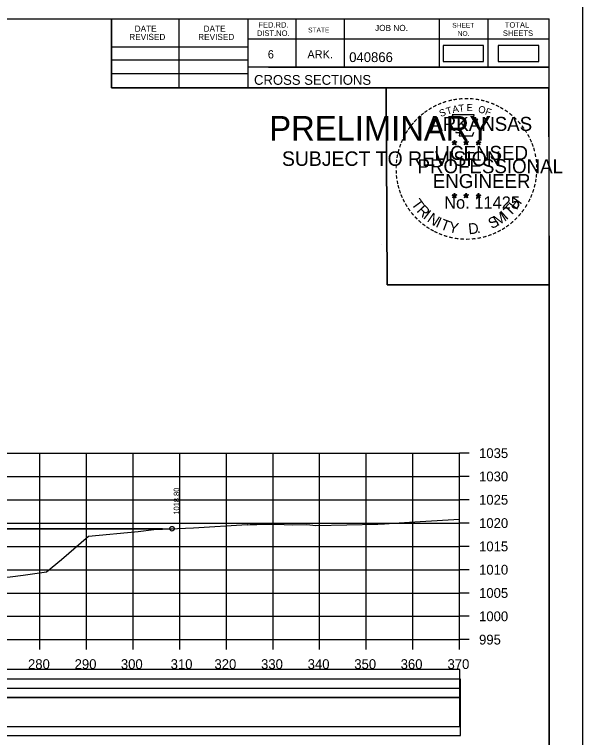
# Model space of a CAD drawing. Extents: x 1370565 to 1374448, y 301010 to 304637.
# Drawn here: x 1374326 to 1374447.9, y 301573 to 301728.1 of the extents above; entities that cross this region are included whole.
import ezdxf

# ---------------------------------------------------------------- set-up
doc = ezdxf.new("R2010")
doc.units = 0
for name, color, linetype in [('Default', 7, 'Continuous'), ('R_Axis', 7, 'Continuous'), ('R_Axis Annot', 7, 'Continuous'), ('R_Border', 7, 'Continuous'), ('R_Border PE', 7, 'Continuous'), ('R_Border Prem', 7, 'Continuous'), ('R_Contours', 7, 'Continuous'), ('R_Drive', 7, 'Continuous'), ('R_Exist Surface', 7, 'Continuous'), ('R_Fin Surface', 7, 'Continuous'), ('R_Grid', 7, 'Continuous'), ('R_No Plot', 7, 'Continuous'), ('R_Xsect Elev', 7, 'Continuous')]:
    doc.layers.add(name, color=color, linetype=linetype)

msp = doc.modelspace()

# ---------------------------------------------------------------- linework, layer by layer
at = {"layer": 'Default'}
for points in [[(1374418.01, 301717.94), (1374426.7, 301717.94), (1374426.7, 301721.38), (1374418.01, 301721.38)], [(1373981.44, 301583.58), (1374421.61, 301583.58), (1374421.61, 301587.57), (1373981.44, 301587.57)], [(1373981.44, 301575.36), (1374421.61, 301575.36), (1374421.61, 301583.5), (1373981.44, 301583.5)]]:
    msp.add_lwpolyline(points, close=True, dxfattribs=at)
at = {"layer": 'R_Axis'}
for p, q in [((1374421.52, 301593.96), (1374421.52, 301633.96)), ((1374423.62, 301633.96), (1374421.52, 301633.96)), ((1374423.62, 301628.96), (1374421.52, 301628.96)), ((1374423.62, 301623.96), (1374421.52, 301623.96)), ((1374423.62, 301618.96), (1374421.52, 301618.96)), ((1374423.62, 301613.96), (1374421.52, 301613.96)), ((1374423.62, 301608.96), (1374421.52, 301608.96)), ((1374423.62, 301603.96), (1374421.52, 301603.96)), ((1374423.62, 301598.96), (1374421.52, 301598.96)), ((1373981.52, 301593.96), (1374421.52, 301593.96)), ((1374331.52, 301591.86), (1374331.52, 301593.96)), ((1374341.52, 301591.86), (1374341.52, 301593.96)), ((1374351.52, 301591.86), (1374351.52, 301593.96)), ((1374361.52, 301591.86), (1374361.52, 301593.96)), ((1374371.52, 301591.86), (1374371.52, 301593.96)), ((1374381.52, 301591.86), (1374381.52, 301593.96)), ((1374391.52, 301591.86), (1374391.52, 301593.96)), ((1374401.52, 301591.86), (1374401.52, 301593.96)), ((1374411.52, 301591.86), (1374411.52, 301593.96)), ((1374421.52, 301591.86), (1374421.52, 301593.96)), ((1374423.62, 301593.96), (1374421.52, 301593.96))]:
    msp.add_line(p, q, dxfattribs=at)
at = {"layer": 'R_Border'}
for p, q in [((1373966.52, 301727.15), (1374440.79, 301727.15)), ((1374346.83, 301712.33), (1374346.83, 301727.15)), ((1374361.35, 301712.33), (1374361.35, 301727.15)), ((1374376.14, 301727.15), (1374376.14, 301712.33)), ((1374386.4, 301727.15), (1374386.4, 301716.74)), ((1374396.81, 301727.15), (1374396.81, 301716.74)), ((1374417.18, 301727.15), (1374417.18, 301716.74)), ((1374427.59, 301727.15), (1374427.59, 301716.74)), ((1374440.79, 301418.96), (1374440.79, 301727.15)), ((1374440.79, 301722.74), (1374376.14, 301722.74)), ((1374440.79, 301722.77), (1374440.79, 301722.77)), ((1374346.83, 301721.12), (1374376.14, 301721.12)), ((1374346.83, 301718.33), (1374376.14, 301718.33)), ((1374440.79, 301716.74), (1374376.14, 301716.74)), ((1374380.58, 301716.74), (1374440.79, 301716.74)), ((1374346.83, 301715.42), (1374376.14, 301715.42)), ((1374440.79, 301712.33), (1374346.83, 301712.33))]:
    msp.add_line(p, q, dxfattribs=at)
at = {"layer": 'R_Border PE'}
for p, q in [((1374419.92, 301700.71), (1374420.44, 301700.54)), ((1374419.92, 301700.71), (1374420.3, 301700.64)), ((1374419.92, 301700.71), (1374420.28, 301700.53)), ((1374420.44, 301701.09), (1374420.38, 301700.71)), ((1374420.44, 301700.54), (1374420.44, 301701.09)), ((1374420.44, 301701.09), (1374420.52, 301700.72)), ((1374420.97, 301700.71), (1374420.44, 301700.54)), ((1374420.97, 301700.71), (1374420.54, 301700.64)), ((1374420.97, 301700.71), (1374420.66, 301700.56)), ((1374422.43, 301700.71), (1374422.95, 301700.54)), ((1374422.43, 301700.71), (1374422.81, 301700.64)), ((1374422.43, 301700.71), (1374422.78, 301700.53)), ((1374422.95, 301701.09), (1374422.89, 301700.71)), ((1374422.95, 301700.54), (1374422.95, 301701.09)), ((1374422.95, 301701.09), (1374423.02, 301700.72)), ((1374423.47, 301700.71), (1374422.95, 301700.54)), ((1374423.47, 301700.71), (1374423.04, 301700.64)), ((1374423.47, 301700.71), (1374423.16, 301700.56)), ((1374425.07, 301700.69), (1374425.6, 301700.52)), ((1374425.07, 301700.69), (1374425.45, 301700.62)), ((1374425.07, 301700.69), (1374425.43, 301700.51)), ((1374425.6, 301701.07), (1374425.53, 301700.69)), ((1374425.6, 301700.52), (1374425.6, 301701.07)), ((1374425.6, 301701.07), (1374425.67, 301700.7)), ((1374426.12, 301700.69), (1374425.6, 301700.52)), ((1374426.12, 301700.69), (1374425.69, 301700.62)), ((1374426.12, 301700.69), (1374425.81, 301700.54)), ((1374420.12, 301700.1), (1374420.44, 301700.54)), ((1374420.12, 301700.1), (1374420.31, 301700.46)), ((1374420.12, 301700.1), (1374420.44, 301700.42)), ((1374420.76, 301700.1), (1374420.44, 301700.54)), ((1374420.76, 301700.1), (1374420.44, 301700.42)), ((1374420.76, 301700.1), (1374420.56, 301700.53)), ((1374422.63, 301700.1), (1374422.95, 301700.54)), ((1374422.63, 301700.1), (1374422.81, 301700.46)), ((1374422.63, 301700.1), (1374422.95, 301700.42)), ((1374423.27, 301700.1), (1374422.95, 301700.54)), ((1374423.27, 301700.1), (1374422.95, 301700.42)), ((1374423.27, 301700.1), (1374423.06, 301700.53)), ((1374425.27, 301700.08), (1374425.6, 301700.52)), ((1374425.27, 301700.08), (1374425.46, 301700.45)), ((1374425.27, 301700.08), (1374425.59, 301700.4)), ((1374425.92, 301700.08), (1374425.59, 301700.4)), ((1374425.92, 301700.08), (1374425.6, 301700.52)), ((1374425.92, 301700.08), (1374425.71, 301700.52)), ((1374420.44, 301689.73), (1374420.38, 301689.35)), ((1374420.44, 301689.18), (1374420.44, 301689.73)), ((1374420.44, 301689.73), (1374420.51, 301689.36)), ((1374422.94, 301689.73), (1374422.88, 301689.35)), ((1374422.94, 301689.18), (1374422.94, 301689.73)), ((1374422.94, 301689.73), (1374423.02, 301689.36)), ((1374425.59, 301689.72), (1374425.53, 301689.34)), ((1374425.59, 301689.17), (1374425.59, 301689.72)), ((1374425.59, 301689.72), (1374425.67, 301689.34)), ((1374419.92, 301689.35), (1374420.44, 301689.18)), ((1374419.92, 301689.35), (1374420.29, 301689.28)), ((1374419.92, 301689.35), (1374420.27, 301689.17)), ((1374420.11, 301688.74), (1374420.44, 301689.18)), ((1374420.11, 301688.74), (1374420.3, 301689.1)), ((1374420.11, 301688.74), (1374420.44, 301689.06)), ((1374420.96, 301689.35), (1374420.44, 301689.18)), ((1374420.76, 301688.74), (1374420.44, 301689.18)), ((1374420.76, 301688.74), (1374420.44, 301689.06)), ((1374420.96, 301689.35), (1374420.53, 301689.28)), ((1374420.76, 301688.74), (1374420.55, 301689.17)), ((1374420.96, 301689.35), (1374420.65, 301689.2)), ((1374422.42, 301689.35), (1374422.94, 301689.18)), ((1374422.42, 301689.35), (1374422.8, 301689.28)), ((1374422.42, 301689.35), (1374422.77, 301689.17)), ((1374422.62, 301688.74), (1374422.94, 301689.18)), ((1374422.62, 301688.74), (1374422.81, 301689.1)), ((1374422.62, 301688.74), (1374422.94, 301689.06)), ((1374423.46, 301689.35), (1374422.94, 301689.18)), ((1374423.26, 301688.74), (1374422.94, 301689.18)), ((1374423.26, 301688.74), (1374422.94, 301689.06)), ((1374423.46, 301689.35), (1374423.03, 301689.28)), ((1374423.26, 301688.74), (1374423.06, 301689.17)), ((1374423.46, 301689.35), (1374423.16, 301689.2)), ((1374425.07, 301689.33), (1374425.59, 301689.17)), ((1374425.07, 301689.33), (1374425.45, 301689.27)), ((1374425.07, 301689.33), (1374425.42, 301689.15)), ((1374425.27, 301688.72), (1374425.59, 301689.17)), ((1374425.27, 301688.72), (1374425.46, 301689.09)), ((1374425.27, 301688.72), (1374425.59, 301689.05)), ((1374426.11, 301689.33), (1374425.59, 301689.17)), ((1374425.91, 301688.72), (1374425.59, 301689.17)), ((1374425.91, 301688.72), (1374425.59, 301689.04)), ((1374426.11, 301689.33), (1374425.68, 301689.26)), ((1374425.91, 301688.72), (1374425.71, 301689.16)), ((1374426.11, 301689.33), (1374425.81, 301689.18))]:
    msp.add_line(p, q, dxfattribs=at)
for points in [[(1374419.98, 301706.53), (1374420.39, 301705.29)], [(1374425.25, 301705.14), (1374425.46, 301705.57), (1374424.43, 301705.53), (1374424.66, 301706.53), (1374419.98, 301706.53)], [(1374420.72, 301702.89), (1374420.72, 301702.76), (1374421.57, 301702.73), (1374421.48, 301702.02), (1374424.29, 301702.02), (1374424.59, 301702.83)], [(1374420.44, 301701.09), (1374420.76, 301700.1), (1374419.92, 301700.71), (1374420.97, 301700.71), (1374420.12, 301700.1), (1374420.44, 301701.09)], [(1374422.95, 301701.09), (1374423.27, 301700.1), (1374422.43, 301700.71), (1374423.47, 301700.71), (1374422.63, 301700.1), (1374422.95, 301701.09)], [(1374425.6, 301701.07), (1374425.92, 301700.08), (1374425.07, 301700.69), (1374426.12, 301700.69), (1374425.27, 301700.08), (1374425.6, 301701.07)], [(1374420.44, 301689.73), (1374420.76, 301688.74), (1374419.92, 301689.35), (1374420.96, 301689.35), (1374420.11, 301688.74), (1374420.44, 301689.73)], [(1374422.94, 301689.73), (1374423.26, 301688.74), (1374422.42, 301689.35), (1374423.46, 301689.35), (1374422.62, 301688.74), (1374422.94, 301689.73)], [(1374425.59, 301689.72), (1374425.91, 301688.72), (1374425.07, 301689.33), (1374426.11, 301689.33), (1374425.27, 301688.72), (1374425.59, 301689.72)]]:
    msp.add_lwpolyline(points, dxfattribs=at)
for centre, radius in [((1374420.44, 301700.54), 0.258), ((1374420.44, 301700.54), 0.217), ((1374420.44, 301700.54), 0.174), ((1374420.44, 301700.54), 0.149), ((1374420.44, 301700.54), 0.112), ((1374420.44, 301700.54), 0.0743), ((1374420.44, 301700.54), 0.0445), ((1374422.95, 301700.54), 0.258), ((1374422.95, 301700.54), 0.217), ((1374422.95, 301700.54), 0.174), ((1374422.95, 301700.54), 0.149), ((1374422.95, 301700.54), 0.112), ((1374422.95, 301700.54), 0.0743), ((1374422.95, 301700.54), 0.0445), ((1374425.59, 301700.52), 0.258), ((1374425.59, 301700.52), 0.217), ((1374425.59, 301700.52), 0.174), ((1374425.59, 301700.52), 0.149), ((1374425.59, 301700.52), 0.112), ((1374425.59, 301700.52), 0.0743), ((1374425.59, 301700.52), 0.0445), ((1374420.44, 301689.18), 0.258), ((1374420.44, 301689.18), 0.217), ((1374420.44, 301689.18), 0.174), ((1374420.44, 301689.18), 0.149), ((1374420.44, 301689.18), 0.112), ((1374420.44, 301689.18), 0.0743), ((1374420.44, 301689.18), 0.0445), ((1374422.94, 301689.18), 0.258), ((1374422.94, 301689.18), 0.217), ((1374422.94, 301689.18), 0.174), ((1374422.94, 301689.18), 0.149), ((1374422.94, 301689.18), 0.112), ((1374422.94, 301689.18), 0.0743), ((1374422.94, 301689.18), 0.0445), ((1374425.59, 301689.17), 0.258), ((1374425.59, 301689.17), 0.217), ((1374425.59, 301689.17), 0.174), ((1374425.59, 301689.17), 0.149), ((1374425.59, 301689.17), 0.112), ((1374425.59, 301689.17), 0.0743), ((1374425.59, 301689.17), 0.0445)]:
    msp.add_circle(centre, radius, dxfattribs=at)
at = {"layer": 'R_Contours'}
for points in [[(1374357.82, 301617.75), (1374352.3, 301617.75), (1374323.59, 301617.72), (1374316.64, 301617.71), (1374313.43, 301617.71), (1374312.94, 301617.71), (1374308.35, 301617.7), (1374305.89, 301617.7), (1374302.51, 301617.7), (1374267.71, 301617.66), (1374265.43, 301617.66), (1374255.43, 301617.65), (1374255.15, 301617.65), (1374242.59, 301617.64), (1374226.41, 301617.62), (1374217.08, 301617.61), (1374209.87, 301617.61), (1374187.8, 301617.58), (1374183.39, 301617.58), (1374156.91, 301617.55), (1374154.16, 301617.55), (1374151.29, 301617.55), (1374124.9, 301617.52), (1374107.34, 301611.73)], [(1374191.74, 301608.89), (1374223.01, 301610.7), (1374227.12, 301611.04), (1374238.52, 301610.45), (1374246.78, 301610.39), (1374256.22, 301610), (1374261.11, 301609.81), (1374267.86, 301608.94), (1374273.25, 301608.14), (1374277.39, 301607.73), (1374278.22, 301607.65), (1374280.75, 301607.58), (1374294.21, 301607.17), (1374297.43, 301607.07), (1374298.23, 301607.05), (1374314.17, 301607.21), (1374325.12, 301607.44), (1374327.89, 301607.77), (1374332.91, 301608.53), (1374336.14, 301611.18), (1374341.9, 301616.12), (1374352.58, 301617.17), (1374355.93, 301617.57), (1374357.82, 301617.66)], [(1374357.82, 301617.66), (1374357.82, 301617.75)]]:
    msp.add_lwpolyline(points, dxfattribs=at)
at = {"layer": 'R_Drive'}
for points in [[(1374429.82, 301717.95), (1374438.51, 301717.95), (1374438.51, 301721.39), (1374429.82, 301721.39)], [(1373981.52, 301581.52), (1374421.73, 301581.52), (1374421.73, 301585.51), (1373981.52, 301585.51)], [(1373981.52, 301573.38), (1374421.73, 301573.38), (1374421.73, 301581.52), (1373981.52, 301581.52)]]:
    msp.add_lwpolyline(points, close=True, dxfattribs=at)
at = {"layer": 'R_Exist Surface'}
msp.add_lwpolyline([(1374325.12, 301607.44), (1374327.89, 301607.77), (1374332.91, 301608.53), (1374336.14, 301611.18), (1374341.9, 301616.12), (1374352.58, 301617.17), (1374355.93, 301617.57), (1374364.46, 301617.97), (1374375.98, 301618.63), (1374376.12, 301618.6), (1374376.12, 301618.6), (1374376.14, 301618.6), (1374376.61, 301618.67), (1374378.01, 301618.69), (1374382.08, 301618.7), (1374385.75, 301618.61), (1374388.75, 301618.65), (1374390.68, 301618.44), (1374404.02, 301618.76), (1374405.45, 301618.83), (1374407.47, 301618.95), (1374413.05, 301619.3), (1374421.52, 301619.81)], dxfattribs=at)
at = {"layer": 'R_Fin Surface'}
msp.add_lwpolyline([(1374187.8, 301617.58), (1374209.87, 301617.61), (1374217.08, 301617.61), (1374226.41, 301617.62), (1374242.59, 301617.64), (1374255.15, 301617.65), (1374255.43, 301617.65), (1374265.43, 301617.66), (1374267.71, 301617.66), (1374302.51, 301617.7), (1374305.89, 301617.7), (1374308.35, 301617.7), (1374312.94, 301617.71), (1374313.43, 301617.71), (1374316.64, 301617.71), (1374323.59, 301617.72), (1374352.3, 301617.75), (1374357.82, 301617.75), (1374359.45, 301617.76), (1374359.86, 301617.76)], dxfattribs=at)
at = {"layer": 'R_Grid'}
for p, q in [((1373981.52, 301633.96), (1374421.52, 301633.96)), ((1374331.52, 301593.96), (1374331.52, 301633.96)), ((1374341.52, 301593.96), (1374341.52, 301633.96)), ((1374351.52, 301593.96), (1374351.52, 301633.96)), ((1374361.52, 301593.96), (1374361.52, 301633.96)), ((1374371.52, 301593.96), (1374371.52, 301633.96)), ((1374381.52, 301593.96), (1374381.52, 301633.96)), ((1374391.52, 301593.96), (1374391.52, 301633.96)), ((1374401.52, 301593.96), (1374401.52, 301633.96)), ((1374411.52, 301593.96), (1374411.52, 301633.96)), ((1374421.52, 301593.96), (1374421.52, 301633.96)), ((1373981.52, 301628.96), (1374421.52, 301628.96)), ((1373981.52, 301623.96), (1374421.52, 301623.96)), ((1373981.52, 301618.96), (1374421.52, 301618.96)), ((1373981.52, 301613.96), (1374421.52, 301613.96)), ((1373981.52, 301608.96), (1374421.52, 301608.96)), ((1373981.52, 301603.96), (1374421.52, 301603.96)), ((1373981.52, 301598.96), (1374421.52, 301598.96)), ((1373981.52, 301593.96), (1374421.52, 301593.96))]:
    msp.add_line(p, q, dxfattribs=at)
at = {"layer": 'R_No Plot'}
msp.add_line((1374404.85, 301678.64), (1374404.85, 301678.64), dxfattribs=at)
for points in [[(1373947.91, 301732.99), (1374447.92, 301732.99), (1374447.92, 301412.98), (1373947.91, 301412.98)], [(1374317.4, 301727.15), (1374346.83, 301727.15), (1374346.83, 301712.33), (1374371, 301712.33), (1374405.8, 301712.33), (1374405.98, 301670.09), (1374440.79, 301670.09), (1374440.79, 301418.96), (1373966.52, 301418.96), (1373966.52, 301727.15)], [(1374405.8, 301712.33), (1374440.61, 301712.33), (1374440.79, 301670.09), (1374405.98, 301670.09)]]:
    msp.add_lwpolyline(points, close=True, dxfattribs=at)
msp.add_circle((1374359.86, 301617.76), 0.5, dxfattribs=at)

# ---------------------------------------------------------------- texts
at = {"layer": 'R_Axis Annot'}
for s, p in [('1035', (1374425.72, 301632.91)), ('1030', (1374425.72, 301627.91)), ('1025', (1374425.72, 301622.91)), ('1020', (1374425.72, 301617.91)), ('1015', (1374425.72, 301612.91)), ('1010', (1374425.72, 301607.91)), ('1005', (1374425.72, 301602.91)), ('1000', (1374425.72, 301597.91)), ('995', (1374425.72, 301592.91)), ('280', (1374328.95, 301587.66)), ('290', (1374338.95, 301587.66)), ('300', (1374348.87, 301587.66)), ('310', (1374359.55, 301587.66)), ('320', (1374368.95, 301587.66)), ('330', (1374378.95, 301587.66)), ('340', (1374388.95, 301587.66)), ('350', (1374398.95, 301587.66)), ('360', (1374408.9, 301587.66)), ('370', (1374418.95, 301587.66))]:
    msp.add_text(s, height=2.1, dxfattribs=at).set_placement(p)
at = {"layer": 'R_Border'}
for s, height, p in [('DATE', 1.319, (1374351.84, 301724.35)), ('DATE', 1.319, (1374366.63, 301724.35)), ('FED.RD.', 1.173, (1374378.36, 301725.23)), ('JOB NO.', 1.319, (1374403.41, 301724.51)), ('SHEET', 1.026, (1374419.97, 301725.23)), ('TOTAL', 1.173, (1374431.25, 301725.23)), ('REVISED', 1.319, (1374350.67, 301722.58)), ('REVISED', 1.319, (1374365.46, 301722.58)), ('DIST.NO.', 1.173, (1374378.06, 301723.46)), ('STATE', 1.026, (1374389.04, 301724.21)), ('NO.', 1.026, (1374421.14, 301723.46)), ('SHEETS', 1.173, (1374430.83, 301723.46)), ('6', 1.76, (1374380.4, 301718.63)), ('ARK.', 1.758, (1374388.89, 301718.63)), ('040866', 2.1, (1374397.86, 301717.85)), ('CROSS SECTIONS', 2.1, (1374377.44, 301712.97))]:
    msp.add_text(s, height=height, rotation=360, dxfattribs=at).set_placement(p)
at = {"layer": 'R_Border PE'}
for s, height, rotation, p in [('-', 2.4, 10.2193, (1374420.25, 301708.82)), ('-', 2.4, 5.8968, (1374421.34, 301708.99)), ('-', 2.4, 0.1862, (1374422.5, 301709.09)), ('-', 2.4, 357.743, (1374423.58, 301709.07)), ('-', 2.4, 352.1617, (1374424.7, 301708.99)), ('-', 2.4, 28.7918, (1374416.2, 301707.34)), ('-', 2.4, 24.3072, (1374417.15, 301707.81)), ('-', 2.4, 19.1761, (1374418.1, 301708.22)), ('T', 1.5, 16.4036, (1374418.89, 301706.54)), ('-', 2.4, 13.6301, (1374419.23, 301708.58)), ('A', 1.5, 11.2132, (1374420.13, 301706.92)), ('T', 1.5, 6.0228, (1374421.4, 301707.17)), ('E', 1.5, 0.8323, (1374423.06, 301707.33)), ('O', 1.5, 350.4515, (1374425.46, 301707.02)), ('-', 2.4, 347.2049, (1374425.78, 301708.82)), ('-', 2.4, 342.3362, (1374426.73, 301708.59)), ('-', 2.4, 337.8551, (1374427.83, 301708.25)), ('-', 2.4, 334.1211, (1374428.78, 301707.85)), ('-', 2.4, 38.9507, (1374413.73, 301705.62)), ('-', 2.4, 36.2317, (1374414.44, 301706.19)), ('-', 2.4, 34.0636, (1374415.31, 301706.78)), ('S', 1.5, 21.594, (1374417.52, 301706.04)), ('F', 1.5, 340.0707, (1374426.89, 301706.67)), ('-', 2.4, 329.6409, (1374429.65, 301707.42)), ('-', 2.4, 325.8627, (1374430.61, 301706.88)), ('-', 2.4, 320.5297, (1374431.53, 301706.24)), ('-', 2.4, 48.4231, (1374412.41, 301704.28)), ('-', 2.4, 42.9622, (1374413.08, 301705)), ('ARKANSAS', 3, 360, (1374415.26, 301703.09)), ('-', 2.4, 315.5786, (1374432.43, 301705.51)), ('-', 2.4, 309.8797, (1374433.28, 301704.68)), ('-', 2.4, 54.2325, (1374411.18, 301702.7)), ('-', 2.4, 50.6142, (1374411.8, 301703.55)), ('-', 2.4, 306.6522, (1374434.07, 301703.78)), ('-', 2.4, 62.8713, (1374410.23, 301700.99)), ('-', 2.4, 58.0706, (1374410.69, 301701.91)), ('-', 2.1, 303.6753, (1374434.8, 301702.93)), ('-', 2.4, 299.6684, (1374435.27, 301702.02)), ('-', 2.4, 67.7743, (1374409.84, 301700.07)), ('DWB', 0.015, 360, (1374420.43, 301700.53)), ('DWB', 0.015, 360, (1374422.93, 301700.53)), ('-', 2.4, 294.6628, (1374435.76, 301701.1)), ('-', 2.4, 75.461, (1374409.21, 301698.06)), ('-', 2.4, 72.3945, (1374409.51, 301699.13)), ('LICENSED', 3, 360, (1374416.16, 301696.87)), ('DWB', 0.015, 360, (1374425.58, 301700.52)), ('-', 2.4, 290.5728, (1374436.15, 301700.24)), ('-', 2.4, 285.1233, (1374436.5, 301699.37)), ('-', 2.4, 81.2013, (1374409.01, 301696.99)), ('-', 2.4, 280.5493, (1374436.8, 301698.25)), ('-', 2.4, 85.1863, (1374408.9, 301695.95)), ('PROFESSIONAL', 3, 360, (1374412.52, 301694.01)), ('-', 2.4, 276.5962, (1374437.04, 301697.1)), ('-', 2.4, 274.3301, (1374437.13, 301696.02)), ('-', 2.4, 94.1959, (1374408.92, 301693.81)), ('-', 2.4, 89.0622, (1374408.86, 301694.9)), ('-', 2.4, 269.9407, (1374437.18, 301695.07)), ('-', 2.4, 98.9479, (1374409.02, 301692.81)), ('ENGINEER', 3, 360, (1374415.8, 301690.83)), ('-', 2.4, 260.9953, (1374437.05, 301693.09)), ('-', 2.4, 263.5172, (1374437.15, 301694.07)), ('-', 2.4, 101.7149, (1374409.23, 301691.71)), ('-', 2.4, 105.4578, (1374409.47, 301690.82)), ('-', 2.4, 255.7626, (1374436.88, 301692.07)), ('-', 2.4, 109.0874, (1374409.79, 301689.87)), ('-', 2.4, 252.8681, (1374436.61, 301690.99)), ('-', 2.4, 114.0643, (1374410.17, 301688.98)), ('-', 2.4, 115.7289, (1374410.63, 301688.05)), ('T', 2.31, 306.0406, (1374411.08, 301687.44)), ('No. 11425', 2.635, 360, (1374418.24, 301686.4)), ('DWB', 0.015, 360, (1374420.42, 301689.18)), ('DWB', 0.015, 360, (1374422.92, 301689.18)), ('DWB', 0.015, 360, (1374425.57, 301689.16)), ('H', 2.31, 54.6088, (1374433.76, 301685.99)), ('-', 2.4, 244.6197, (1374435.88, 301689.04)), ('-', 2.4, 247.8887, (1374436.27, 301689.98)), ('-', 2.4, 120.4471, (1374411.17, 301687.17)), ('-', 2.4, 125.8934, (1374411.77, 301686.33)), ('R', 2.31, 314.005, (1374412.22, 301685.87)), ('T', 2.31, 46.6444, (1374432.42, 301684.58)), ('-', 2.4, 239.0712, (1374435.29, 301687.91)), ('-', 2.4, 130.7181, (1374412.46, 301685.5)), ('I', 2.31, 321.9694, (1374413.57, 301684.47)), ('N', 2.31, 326.5002, (1374414.42, 301683.76)), ('M', 2.31, 32.6563, (1374429.66, 301682.59)), ('I', 2.31, 42.1136, (1374431.58, 301683.86)), ('-', 2.4, 231.2538, (1374434.04, 301686.08)), ('-', 2.4, 233.8452, (1374434.69, 301686.93)), ('-', 2.4, 134.2238, (1374413.24, 301684.69)), ('-', 2.4, 138.9338, (1374414.03, 301683.99)), ('I', 2.31, 335.3603, (1374416.24, 301682.58)), ('T', 2.31, 339.8912, (1374417.23, 301682.09)), ('Y', 2.31, 347.8556, (1374419.05, 301681.43)), ('S', 2.31, 26.9312, (1374428.4, 301681.98)), ('-', 2.4, 221.0851, (1374432.54, 301684.47)), ('-', 2.4, 225.7653, (1374433.32, 301685.24)), ('-', 2.4, 144.6463, (1374414.86, 301683.38)), ('-', 2.4, 148.0898, (1374415.7, 301682.82)), ('-', 2.4, 151.5704, (1374416.57, 301682.34)), ('D', 2.31, 6.3969, (1374423.53, 301680.89)), ('-', 2.4, 212.2491, (1374430.92, 301683.18)), ('-', 2.4, 215.7363, (1374431.72, 301683.77)), ('-', 2.4, 154.6002, (1374417.35, 301681.97)), ('-', 2.4, 158.5612, (1374418.29, 301681.59)), ('-', 2.4, 162.7983, (1374419.32, 301681.27)), ('-', 2.4, 167.5555, (1374420.39, 301681.02)), ('.', 2.31, 13.7642, (1374425.32, 301681.08)), ('-', 2.4, 195.4743, (1374427.2, 301681.41)), ('-', 2.4, 200.7184, (1374428.21, 301681.78)), ('-', 2.4, 204.2516, (1374429.14, 301682.19)), ('-', 2.4, 207.3568, (1374430.08, 301682.67)), ('-', 2.4, 173.1155, (1374421.55, 301680.86)), ('-', 2.4, 176.5183, (1374422.67, 301680.78)), ('-', 2.4, 181.5918, (1374423.79, 301680.8)), ('-', 2.4, 185.8167, (1374425, 301680.92)), ('-', 2.4, 191.2858, (1374426.11, 301681.12))]:
    msp.add_text(s, height=height, rotation=rotation, dxfattribs=at).set_placement(p)
at = {"layer": 'R_Border Prem'}
for s, height, p in [('PRELIMINARY', 5.25, (1374380.72, 301701.02)), ('DWB', 0.015, (1374381.84, 301703.8)), ('SUBJECT TO REVISION', 3.1127, (1374383.43, 301695.58))]:
    msp.add_text(s, height=height, rotation=360, dxfattribs=at).set_placement(p)
at = {"layer": 'R_Xsect Elev'}
msp.add_text('1018.80', height=1.2, rotation=90, dxfattribs=at).set_placement((1374361.41, 301620.76))

doc.saveas('drawing.dxf')
